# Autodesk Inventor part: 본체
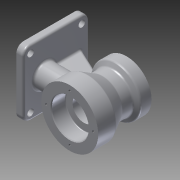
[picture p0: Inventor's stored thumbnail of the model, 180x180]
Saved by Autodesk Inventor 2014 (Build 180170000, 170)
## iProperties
Created: 2019-01
Part Number: 본체
Material: 알루미늄 6061
Document SubType Name: Modeling
Designer: kh
Density: 2.71 g/cm^3
Appearance: 알루미늄 - 평지
Mass: 898.98 g
Surface Area: 601.454 cm^2
Volume: 331.727 cm^3
Author: kh
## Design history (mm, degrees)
sketch "스케치3"
  geometry: L1 (0, 0)-(80, 0); L2 (0, 0)-(0, 40); L3 (0, 40)-(25, 40); L4 (25, 40)-(45.785, 28); L5 (45.785, 28)-(60.959, 28); L6 (60.959, 28)-(65, 35); L7 (65, 35)-(80, 35); L8 (80, 35)-(80, 0); L9 (0, 26)-(20, 26); L10 (20, 26)-(20, 16); L11 (20, 16)-(63, 16); L12 (63, 16)-(63, 20); L13 (63, 20)-(80, 20)
  constraints: 26 end point, 9 perpendicular, 2 parallel, 2 point on line, 1 horizontal
  dimensions: "d10" = 80 distance of L1.start L1.end; "d12" = 25 distance of L2.end L3.end; "d13" = 15 distance of L6.end L7.end; "d17" = 70 diameter of L7 L1; "d19" = 52 diameter of L9 L1; "d22" = 32 diameter of L11 L1; "d23" = 20 distance of L9.start L9.end; "d24" = 17 distance of L12.end L13.end; "d25" = 40 diameter of L13 L1; "d26" = 56 diameter of L5 L1; "d27" = 80 diameter of L3 L1; "d28" = 30 deg angle of L5 L4
revolve "회전1" sketch "스케치3" stored, may be unused: angle "d29" = 90 deg
node "작업 평면3"
sketch "스케치4"
  geometry: L1 (0, 0)-(5, 0); L2 (5, 46)-(97, 46); L3 (97, 46)-(97, -46); L4 (97, -46)-(5, -46); L5 (5, -46)-(5, 46); L6 (5, 46)-(97, -46); L7 (97, 46)-(5, -46); 1 further point
  constraints: 14 end point, 3 midpoint, 2 horizontal, 2 parallel, 1 perpendicular
  dimensions: "d31" = 5 distance of L1.end L1.start; "d32" = 92 distance of L2.start L2.end; "d33" = 92 distance of L2.end L3.end
extrude "돌출3" join sketch "스케치4" distance "d34" = 10; taper "d35" = 0 deg
sketch "스케치5"
  geometry: L1 (-46, 5)-(46, 5) reference; L2 (46, 97)-(-46, 97) reference; L3 (0, 5)-(0, 35); C1 r 16 at (0, 35); 1 further point
  constraints: 2 end point, 1 centre point, 1 coincident, 1 midpoint, 1 perpendicular
  dimensions: "d36" = 30 distance of L3.start L3.end; "d37" = 32 diameter of C1
extrude "돌출4" join sketch "스케치5" stored distance "d38" = 10; taper "d39" = 0 deg
sketch "스케치6"
  geometry: L1 (-80, 97)-(-80, 5) reference; L2 (-80, 97)-(-70, 97) reference; L3 (-70, 5)-(-70, 97) reference; L4 (-80, 5)-(-70, 5) reference; L5 (-70, 87)-(-45.508, 75.579); 1 further point
  constraints: 2 end point, 1 point on line
  dimensions: "d40" = 10 distance of L2.end L5.start; "d41" = 25 deg angle of L2 L5
feature "리브1" sketch "스케치6" dims "d42" = 1, "d43" = 10, "d44" = 0, "d45" = 0, "d46" = 1, "d47" = 1
fillet "모깎기1" dims "d48" = 10
hole "구멍1" diameter "d51" = 9; stored, may be unused: countersink angle "d55" = 90 deg, drill point angle "d57" = 118 deg; dims "d49" = 10, "d50" = 10, "d52" = 6, "d53" = 4, "d54" = 2, "d56" = 8
hole "구멍2" diameter "d60" = 9; stored, may be unused: countersink angle "d64" = 90 deg, drill point angle "d66" = 118 deg; dims "d58" = 10, "d59" = 10, "d61" = 6, "d62" = 4, "d63" = 2, "d65" = 8
hole "구멍3" diameter "d69" = 9; stored, may be unused: countersink angle "d73" = 90 deg, drill point angle "d75" = 118 deg; dims "d67" = 10, "d68" = 10, "d70" = 6, "d71" = 4, "d72" = 2, "d74" = 8
hole "구멍4" diameter "d78" = 9; stored, may be unused: countersink angle "d82" = 90 deg, drill point angle "d84" = 118 deg; dims "d76" = 10, "d77" = 10, "d79" = 6, "d80" = 4, "d81" = 2, "d83" = 8
node "작업 평면4"
fillet "모깎기2" dims "d89" = 3
fillet "모깎기3" dims "d90" = 3
fillet "모깎기4" dims "d91" = 3
fillet "모깎기5" dims "d92" = 0.6
fillet "모깎기6" dims "d93" = 1
chamfer "모따기1" distance "d94" = 1; stored, may be unused: second distance "d95" = 2, angle "d96" = 45 deg
node "작업 평면5"
sketch "스케치8"
  geometry: L1 (-5.947, 22.076)-(-5.992, 49.917); L2 (-5.992, 49.917)-(-2.053, 49.924); L3 (-2.053, 49.924)-(-2.008, 22.083); L4 (-2.008, 22.083)-(-5.947, 22.076); L5 (-2.008, 22.083)-(-5.992, 49.917); L6 (-7, -10)-(0, -10) reference; L7 (0, -10)-(-4, -10); L8 (-4, -10)-(-4, 36); 1 further point
  constraints: 6 end point, 1 midpoint, 1 point on line, 1 vertical, 2 other
  dimensions: "d98" = 4 distance of L6.end L7.end; "d99" = 46 distance of L8.end L7.end
feature "엠보싱2" sketch "스케치8" dims "d10" = 80, "d12" = 25, "d13" = 15, "d17" = 70, "d19" = 52, "d22" = 32, "d23" = 20, "d24" = 17, "d25" = 40, "d26" = 56, "d27" = 80, "d28" = 30 deg, "d31" = 5, "d32" = 92, "d33" = 92, "d100" = 0.5, "d101" = 0
sketch "스케치9" dims "d102" = 66
  geometry: L1 (0, 0)-(33, 0); C1 r 27 at (0, 0) reference; 1 further point
  constraints: 2 coincident, 2 end point, 1 horizontal, 1 horizontal alignment, 2 other
hole "구멍5" sketch "스케치9" at (33, 0) diameter "d103" = 3.242; stored, may be unused: countersink angle "d107" = 90 deg, drill point angle "d109" = 118 deg; dims "d104" = 9, "d105" = 4, "d106" = 2, "d108" = 11
sketch "스케치10" dims "d113" = 55
  geometry: L1 (0, 0)-(27.5, 0); C1 r 21 at (0, 0) reference; 1 further point
  constraints: 2 coincident, 2 end point, 1 horizontal, 1 horizontal alignment, 2 other
hole "구멍6" sketch "스케치10" at (27.5, 0) diameter "d114" = 3.242; stored, may be unused: countersink angle "d118" = 90 deg, drill point angle "d120" = 118 deg; dims "d115" = 9, "d116" = 4, "d117" = 2, "d119" = 11
node "솔리드2"
pattern_circular "원형 패턴1" dims angle "d111" = 360 deg
pattern_circular "원형 패턴2" dims angle "d122" = 360 deg
node "투영된 루프2"
other parameters: "d85" = 12, "d97" = 9.25
